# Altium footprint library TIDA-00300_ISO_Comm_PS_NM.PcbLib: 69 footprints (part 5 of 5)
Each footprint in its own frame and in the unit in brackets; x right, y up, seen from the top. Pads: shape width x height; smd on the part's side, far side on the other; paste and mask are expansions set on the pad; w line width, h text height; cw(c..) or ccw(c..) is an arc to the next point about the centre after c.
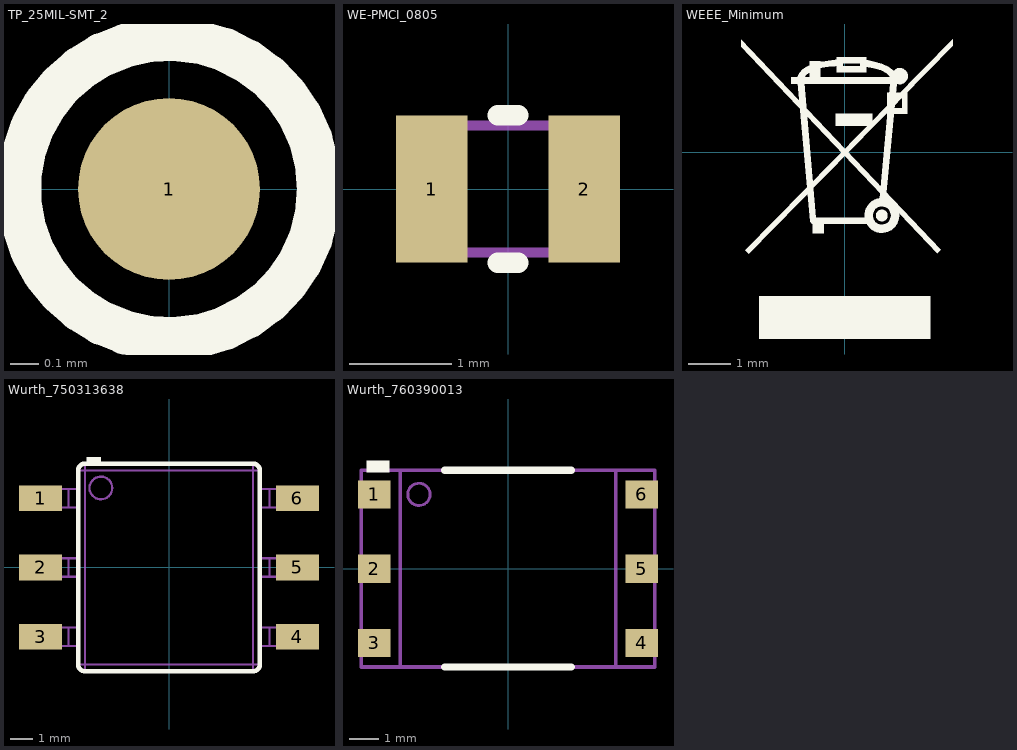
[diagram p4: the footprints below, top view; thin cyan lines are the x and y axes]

## TP_25MIL-SMT_2 [mm]
pads (1):
  round 0.635 smd mask-0.064: 1(0,0)
Top Overlay:
  circle w0.152: c0,0 r0.524

## WE-PMCI_0805 [mm] "SMD, 2-Leads, Body 2x1.25mm"
height 1
pads (2):
  rect 0.7x1.45 smd: 1(-0.75,0) 2(0.75,0)
Top Overlay:
  lines w0.2: -0.1,-0.725 0.1,-0.725 ; -0.1,0.725 0.1,0.725
Mechanical 5:
  lines w0.1: -1,-0.625 -1,0.625 -0.5,0.625 0.5,0.625 1,0.625 1,-0.625 0.5,-0.625 -0.5,-0.625 -1,-0.625
  text ".Designator" at -0.572,-0.265 h0.51
3D body "PMCI-0805.stp": height 1, standoff 0, extent -1,-0.625 1,0.625

## WEEE_Minimum [mm] "WEEElie bin"
Top Overlay:
  drawing of 23 lines, arcs and shapes, not listed

## Wurth_750313638 [mm] "SMD, 6-Leads, Body 8x9.14mm, Pitch 3.05mm"
height 7.62
pads (6):
  rect 1.9x1.14 smd: 1(-5.655,3.05) 2(-5.655,0) 3(-5.655,-3.05) 4(5.655,-3.05) 5(5.655,0) 6(5.655,3.05)
Top Overlay:
  rectangle: -3.625,4.57 -3,4.875
  lines w0.2: -4,-4.27 ccw(c-3.7,-4.27) -3.7,-4.57 3.7,-4.57 ccw(c3.7,-4.27) 4,-4.27 4,4.27 ccw(c3.7,4.27) 3.7,4.57 -3.7,4.57 ccw(c-3.7,4.27) -4,4.27 -4,-4.27
Mechanical 5:
  circle w0.1: c-3,3.5 r0.5
  lines w0.1: -4,-3.455 -4.43,-3.455 ; -4,-2.645 -4.43,-2.645 ; -4,-0.405 -4.43,-0.405 ; -4,0.405 -4.43,0.405 ; -4,2.645 -4.43,2.645 ; -4,3.455 -4.43,3.455 ; 4,-3.455 4.43,-3.455 ; 4,-2.645 4.43,-2.645 ; 4,-0.405 4.43,-0.405 ; 4,0.405 4.43,0.405 ; 4,2.645 4.43,2.645 ; 4,3.455 4.43,3.455 ; -5.47,-3.455 -5.47,-2.645 ; -5.47,-3.455 -6.35,-3.455 -6.35,-2.645 -5.47,-2.645 ; -5.47,-3.455 -5.376,-3.455 ; -5.47,-2.645 -5.376,-2.645 ; -5.47,-0.405 -5.47,0.405 ; -5.47,-0.405 -5.376,-0.405 ; -5.47,-0.405 -6.35,-0.405 -6.35,0.405 -5.47,0.405 ; -5.47,0.405 -5.376,0.405 ; -5.47,2.645 -5.47,3.455 ; -5.47,2.645 -6.35,2.645 -6.35,3.455 -5.47,3.455 ; -5.47,2.645 -5.376,2.645 ; -5.47,3.455 -5.376,3.455 ; -5.376,-3.455 -5.376,-2.645 ; -5.376,-3.455 -4.9,-3.455 ; -5.376,-2.645 -4.9,-2.645 ; -5.376,-0.405 -5.376,0.405 ; -5.376,-0.405 -4.9,-0.405 ; -5.376,0.405 -4.9,0.405 ; -5.376,2.645 -5.376,3.455 ; -5.376,2.645 -4.9,2.645 ; -5.376,3.455 -4.9,3.455 ; -4.9,-3.455 -4.9,-2.645 ; -4.9,-3.455 -4.43,-3.455 ; -4.9,-2.645 -4.43,-2.645 ; -4.9,-0.405 -4.9,0.405 ; -4.9,-0.405 -4.43,-0.405 ; -4.9,0.405 -4.43,0.405 ; -4.9,2.645 -4.9,3.455 ; -4.9,2.645 -4.43,2.645 ; -4.9,3.455 -4.43,3.455 ; -4.43,-3.455 -4.43,-2.645 ; -4.43,-0.405 -4.43,0.405 ; -4.43,2.645 -4.43,3.455 ; -4,-4.27 ccw(c-3.7,-4.27) -3.7,-4.57 ; -4,-4.27 -3.7,-4.27 ; -4,-4.27 -4,4.27 ; -4,4.27 cw(c-3.7,4.27) -3.7,4.57 ; -4,4.27 -3.7,4.27 ; -3.7,-4.57 -3.7,-4.27 ; -3.7,-4.57 3.7,-4.57 ; -3.7,-4.27 3.7,-4.27 ; -3.7,-4.27 -3.7,4.27 ; -3.7,4.27 -3.7,4.57 ; -3.7,4.27 3.7,4.27 ; -3.7,4.57 3.7,4.57 ; 3.7,-4.57 ccw(c3.7,-4.27) 4,-4.27 ; 3.7,-4.57 3.7,-4.27 ; 3.7,-4.27 4,-4.27 ; 3.7,-4.27 3.7,4.27 ; 3.7,4.27 4,4.27 ; 3.7,4.27 3.7,4.57 ; 3.7,4.57 cw(c3.7,4.27) 4,4.27 ; 4,-4.27 4,4.27 ; 4.43,-3.455 4.43,-2.645 ; 4.43,-3.455 4.9,-3.455 ; 4.43,-2.645 4.9,-2.645 ; 4.43,-0.405 4.43,0.405 ; 4.43,-0.405 4.9,-0.405 ; 4.43,0.405 4.9,0.405 ; 4.43,2.645 4.43,3.455 ; 4.43,2.645 4.9,2.645 ; 4.43,3.455 4.9,3.455 ; 4.9,-3.455 4.9,-2.645 ; 4.9,-3.455 5.376,-3.455 ; 4.9,-2.645 5.376,-2.645 ; 4.9,-0.405 4.9,0.405 ; 4.9,-0.405 5.376,-0.405 ; 4.9,0.405 5.376,0.405 ; 4.9,2.645 4.9,3.455 ; 4.9,2.645 5.376,2.645 ; 4.9,3.455 5.376,3.455 ; 5.376,-3.455 5.376,-2.645 ; 5.376,-3.455 5.47,-3.455 ; 5.376,-2.645 5.47,-2.645 ; 5.376,-0.405 5.376,0.405 ; 5.376,-0.405 5.47,-0.405 ; 5.376,0.405 5.47,0.405 ; 5.376,2.645 5.376,3.455 ; 5.376,2.645 5.47,2.645 ; 5.376,3.455 5.47,3.455 ; 5.47,-3.455 5.47,-2.645 ; 5.47,-3.455 6.35,-3.455 6.35,-2.645 5.47,-2.645 ; 5.47,-0.405 5.47,0.405 ; 5.47,-0.405 6.35,-0.405 6.35,0.405 5.47,0.405 ; 5.47,2.645 5.47,3.455 ; 5.47,2.645 6.35,2.645 6.35,3.455 5.47,3.455
  text ".Designator" at -0.374,0.123 h0.51
3D body "750313638.stp": height 7.62, standoff 0, extent -6.35,-4.57 6.35,4.57

## Wurth_760390013 [mil] "Wurth"
height 165
pads (6):
  rect 44x38 smd: 1(-180,100) 2(-180,0) 3(-180,-100) 4(180,-100) 5(180,0) 6(180,100)
Top Overlay:
  region: -190,145 -160,145 -160,130 -190,130
  lines w10: -85,-132.5 85,-132.5 ; -85,132.5 85,132.5
Mechanical 5:
  circle w3.94: c-120,100 r15
  lines w5: -145,-130 -145,130 ; 145,-130 145,130 ; -197.5,-132.5 197.5,-132.5 197.5,132.5 -197.5,132.5 -197.5,-132.5
  text ".Designator" at -8,-10 h20
3D body: height 20, standoff 0, extent -197.14,85 -145,115
3D body: height 20, standoff 0, extent -197.63,-15 -145,15
3D body: height 20, standoff 0, extent -197.63,-115 -145,-85
3D body: height 20, standoff 0, extent 145,85 197.5,115
3D body: height 20, standoff 0, extent 145,-15 197.5,15
3D body: height 20, standoff 0, extent 143.75,-115 196.25,-85
3D body: height 165.5, standoff 150, extent -134.98,85.02 -105.02,114.98
3D body: height 165, standoff 0, extent -145,-135 145,130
